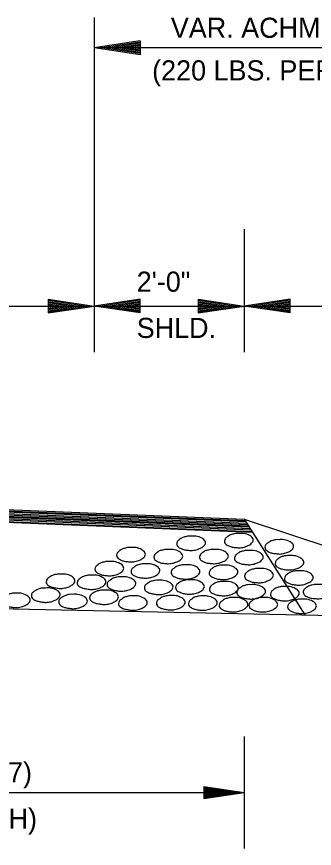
# Model space of a CAD drawing. Extents: x 1035 to 3550, y 35 to 1510.
# Drawn here: x 2489.7 to 2578.4, y 579 to 826.9 of the extents above; entities that cross this region are included whole.
import ezdxf

# ---------------------------------------------------------------- set-up
doc = ezdxf.new("R2010")
doc.units = 0
doc.layers.add('Default', color=7, linetype='Continuous')

msp = doc.modelspace()

# ---------------------------------------------------------------- linework, layer by layer
at = {"layer": 'Default'}
for p, q in [((2512.84, 826.63), (2512.84, 763.6)), ((2526.54, 819.67), (2512.84, 817.63)), ((2526.54, 819.34), (2515.11, 817.63)), ((2526.54, 818.99), (2517.48, 817.63)), ((2526.54, 818.66), (2519.76, 817.63)), ((2526.54, 818.27), (2522.08, 817.63)), ((2526.54, 819.67), (2526.54, 815.57)), ((2526.54, 815.57), (2512.84, 817.63)), ((2745.94, 817.63), (2512.84, 817.63)), ((2526.54, 815.92), (2515.11, 817.63)), ((2526.54, 816.26), (2517.48, 817.63)), ((2526.54, 816.62), (2519.76, 817.63)), ((2526.54, 816.95), (2522.08, 817.63)), ((2526.54, 817.96), (2524.35, 817.63)), ((2526.54, 817.3), (2524.35, 817.63)), ((2512.84, 763.6), (2512.84, 726.95)), ((2557.51, 763.6), (2557.51, 726.95)), ((2499.16, 742.69), (2512.84, 740.65)), ((2499.16, 742.69), (2499.16, 738.59)), ((2499.16, 742.36), (2510.55, 740.65)), ((2499.16, 742), (2508.21, 740.65)), ((2499.16, 741.67), (2505.94, 740.65)), ((2499.16, 741.3), (2503.58, 740.65)), ((2526.54, 742.69), (2512.84, 740.65)), ((2526.54, 742.36), (2515.12, 740.65)), ((2526.54, 742), (2517.47, 740.65)), ((2526.54, 741.67), (2519.76, 740.65)), ((2526.54, 741.3), (2522.07, 740.65)), ((2526.54, 738.59), (2526.54, 742.69)), ((2543.83, 742.69), (2557.51, 740.65)), ((2543.83, 742.69), (2543.83, 738.59)), ((2543.83, 742.36), (2555.22, 740.65)), ((2543.83, 742), (2552.88, 740.65)), ((2543.83, 741.67), (2550.61, 740.65)), ((2543.83, 741.3), (2548.25, 740.65)), ((2571.21, 742.69), (2557.51, 740.65)), ((2571.21, 742.36), (2559.79, 740.65)), ((2571.21, 742), (2562.14, 740.65)), ((2571.21, 741.67), (2564.43, 740.65)), ((2571.21, 741.3), (2566.74, 740.65)), ((2571.21, 738.59), (2571.21, 742.69)), ((2335.41, 740.65), (2512.84, 740.65)), ((2499.16, 740.97), (2501.31, 740.65)), ((2499.16, 738.59), (2512.84, 740.65)), ((2499.16, 739.96), (2503.58, 740.65)), ((2499.16, 739.27), (2508.21, 740.65)), ((2499.16, 738.93), (2510.55, 740.65)), ((2499.16, 739.63), (2505.94, 740.65)), ((2499.16, 740.32), (2501.31, 740.65)), ((2512.84, 740.65), (2557.51, 740.65)), ((2526.54, 738.59), (2512.84, 740.65)), ((2526.54, 738.93), (2515.12, 740.65)), ((2526.54, 739.27), (2517.47, 740.65)), ((2526.54, 739.63), (2519.76, 740.65)), ((2526.54, 739.96), (2522.07, 740.65)), ((2526.54, 740.97), (2524.34, 740.65)), ((2526.54, 740.32), (2524.34, 740.65)), ((2543.83, 740.97), (2545.98, 740.65)), ((2543.83, 738.59), (2557.51, 740.65)), ((2543.83, 739.96), (2548.25, 740.65)), ((2543.83, 739.27), (2552.88, 740.65)), ((2543.83, 738.93), (2555.22, 740.65)), ((2543.83, 739.63), (2550.61, 740.65)), ((2543.83, 740.32), (2545.98, 740.65)), ((2557.51, 740.65), (2647.44, 740.65)), ((2571.21, 738.59), (2557.51, 740.65)), ((2571.21, 738.93), (2559.79, 740.65)), ((2571.21, 739.27), (2562.14, 740.65)), ((2571.21, 739.63), (2564.43, 740.65)), ((2571.21, 739.96), (2566.74, 740.65)), ((2571.21, 740.97), (2569.01, 740.65)), ((2571.21, 740.32), (2569.01, 740.65)), ((2512.84, 733.81), (2512.84, 726.95)), ((2330.33, 686.31), (2557.51, 677.18)), ((2330.33, 685.87), (2557.79, 676.73)), ((2330.33, 685.54), (2557.97, 676.45)), ((2330.33, 685.12), (2558.27, 675.98)), ((2330.33, 684.7), (2558.52, 675.59)), ((2330.33, 684.34), (2558.81, 675.13)), ((2330.33, 683.96), (2559.01, 674.8)), ((2330.33, 683.58), (2559.3, 674.35)), ((2330.33, 683.16), (2559.55, 673.96)), ((2330.33, 682.79), (2559.84, 673.5)), ((2330.33, 682.46), (2560.01, 673.24)), ((2557.51, 677.18), (2575.62, 648.63)), ((2557.51, 677.18), (2755.04, 611.33)), ((2261.14, 654.92), (2647.44, 647.2)), ((2557.51, 612.37), (2557.51, 579.01)), ((2545.51, 597.49), (2557.51, 595.69)), ((2545.51, 597.49), (2545.51, 593.89)), ((2355.29, 595.69), (2557.51, 595.69)), ((2545.51, 597.19), (2555.51, 595.69)), ((2545.51, 596.88), (2553.44, 595.69)), ((2545.51, 596.58), (2551.44, 595.69)), ((2545.51, 596.27), (2549.41, 595.69)), ((2545.51, 595.97), (2547.41, 595.69)), ((2545.51, 593.89), (2557.51, 595.69)), ((2545.51, 595.1), (2549.41, 595.69)), ((2545.51, 594.5), (2553.44, 595.69)), ((2545.51, 594.19), (2555.51, 595.69)), ((2545.51, 594.8), (2551.44, 595.69)), ((2545.51, 595.41), (2547.41, 595.69))]:
    msp.add_line(p, q, dxfattribs=at)
for points in [[(2541.65, 672.07), (2543.13, 672.05), (2544.97, 671.43), (2545.86, 670.55), (2546.01, 670.04), (2545.51, 669.14), (2544.98, 668.7), (2544, 668.25), (2542.51, 667.86), (2541.76, 667.81), (2540.64, 667.89), (2539.42, 668.09), (2538.47, 668.48), (2537.57, 669.18), (2537.43, 669.79), (2537.71, 670.59), (2538.38, 671.16), (2539.03, 671.6), (2540.04, 671.89), (2540.65, 672.05), (2541.65, 672.07)], [(2555.88, 672.88), (2557.36, 672.86), (2559.2, 672.24), (2560.09, 671.36), (2560.24, 670.85), (2559.74, 669.95), (2559.21, 669.51), (2558.23, 669.06), (2556.74, 668.67), (2555.99, 668.62), (2554.87, 668.7), (2553.65, 668.9), (2552.7, 669.29), (2551.8, 669.99), (2551.66, 670.6), (2551.94, 671.4), (2552.61, 671.97), (2553.26, 672.41), (2554.27, 672.7), (2554.88, 672.86), (2555.88, 672.88)], [(2567.9, 671.02), (2569.43, 671.01), (2571.25, 670.37), (2572.14, 669.54), (2572.26, 669), (2571.8, 668.08), (2571.28, 667.69), (2570.28, 667.17), (2568.82, 666.83), (2568.06, 666.75), (2566.95, 666.86), (2565.69, 667.07), (2564.74, 667.44), (2563.86, 668.17), (2563.71, 668.75), (2563.97, 669.57), (2564.67, 670.1), (2565.31, 670.52), (2566.33, 670.87), (2566.96, 671.01), (2567.9, 671.02)], [(2523.75, 668.66), (2525.23, 668.64), (2527.07, 668.02), (2527.96, 667.14), (2528.11, 666.63), (2527.61, 665.73), (2527.08, 665.29), (2526.1, 664.84), (2524.61, 664.45), (2523.86, 664.4), (2522.74, 664.48), (2521.52, 664.68), (2520.57, 665.07), (2519.67, 665.77), (2519.53, 666.38), (2519.81, 667.18), (2520.48, 667.75), (2521.13, 668.19), (2522.14, 668.48), (2522.75, 668.64), (2523.75, 668.66)], [(2534.86, 668.12), (2536.34, 668.1), (2538.18, 667.48), (2539.07, 666.6), (2539.22, 666.09), (2538.72, 665.19), (2538.19, 664.75), (2537.21, 664.3), (2535.72, 663.91), (2534.97, 663.86), (2533.85, 663.94), (2532.63, 664.14), (2531.68, 664.53), (2530.78, 665.23), (2530.64, 665.84), (2530.92, 666.64), (2531.59, 667.21), (2532.24, 667.65), (2533.25, 667.94), (2533.86, 668.1), (2534.86, 668.12)], [(2548.45, 668.12), (2549.93, 668.1), (2551.77, 667.48), (2552.66, 666.6), (2552.81, 666.09), (2552.31, 665.19), (2551.78, 664.75), (2550.8, 664.3), (2549.31, 663.91), (2548.56, 663.86), (2547.44, 663.94), (2546.22, 664.14), (2545.27, 664.53), (2544.37, 665.23), (2544.23, 665.84), (2544.51, 666.64), (2545.18, 667.21), (2545.83, 667.65), (2546.84, 667.94), (2547.45, 668.1), (2548.45, 668.12)], [(2558.85, 667.82), (2560.33, 667.8), (2562.17, 667.18), (2563.06, 666.3), (2563.21, 665.79), (2562.71, 664.89), (2562.18, 664.45), (2561.2, 664), (2559.71, 663.61), (2558.96, 663.56), (2557.84, 663.64), (2556.62, 663.84), (2555.67, 664.23), (2554.77, 664.93), (2554.63, 665.54), (2554.91, 666.34), (2555.58, 666.91), (2556.23, 667.35), (2557.24, 667.64), (2557.85, 667.8), (2558.85, 667.82)], [(2517.27, 664.5), (2518.8, 664.49), (2520.62, 663.85), (2521.51, 663.02), (2521.63, 662.48), (2521.17, 661.56), (2520.65, 661.17), (2519.65, 660.65), (2518.19, 660.31), (2517.43, 660.23), (2516.32, 660.34), (2515.06, 660.55), (2514.11, 660.92), (2513.23, 661.65), (2513.08, 662.23), (2513.34, 663.05), (2514.04, 663.58), (2514.68, 664), (2515.7, 664.35), (2516.33, 664.49), (2517.27, 664.5)], [(2570.94, 666.26), (2572.45, 666.24), (2574.26, 665.62), (2575.16, 664.75), (2575.32, 664.25), (2574.84, 663.31), (2574.31, 662.89), (2573.32, 662.44), (2571.84, 662.05), (2571.08, 661.99), (2569.96, 662.07), (2568.73, 662.29), (2567.78, 662.67), (2566.9, 663.38), (2566.75, 663.98), (2567.01, 664.78), (2567.7, 665.36), (2568.34, 665.79), (2569.37, 666.1), (2569.99, 666.24), (2570.94, 666.26)], [(2528.03, 663.8), (2529.56, 663.79), (2531.38, 663.15), (2532.27, 662.32), (2532.39, 661.78), (2531.93, 660.86), (2531.41, 660.47), (2530.41, 659.95), (2528.95, 659.61), (2528.19, 659.53), (2527.08, 659.64), (2525.82, 659.85), (2524.87, 660.22), (2523.99, 660.95), (2523.84, 661.53), (2524.1, 662.35), (2524.8, 662.88), (2525.44, 663.3), (2526.46, 663.65), (2527.09, 663.79), (2528.03, 663.8)], [(2539.95, 663.53), (2541.49, 663.49), (2543.32, 662.88), (2544.21, 662.01), (2544.31, 661.51), (2543.85, 660.56), (2543.33, 660.15), (2542.35, 659.67), (2540.87, 659.31), (2540.11, 659.25), (2539, 659.34), (2537.78, 659.56), (2536.82, 659.93), (2535.93, 660.64), (2535.77, 661.24), (2536.04, 662.07), (2536.73, 662.6), (2537.38, 663.04), (2538.38, 663.36), (2539.02, 663.49), (2539.95, 663.53)], [(2551.27, 663.41), (2552.78, 663.39), (2554.6, 662.75), (2555.52, 661.9), (2555.66, 661.4), (2555.16, 660.46), (2554.63, 660.04), (2553.67, 659.56), (2552.16, 659.19), (2551.42, 659.14), (2550.29, 659.22), (2549.07, 659.43), (2548.12, 659.82), (2547.23, 660.53), (2547.09, 661.15), (2547.36, 661.93), (2548.04, 662.49), (2548.7, 662.93), (2549.68, 663.25), (2550.3, 663.39), (2551.27, 663.41)], [(2561.87, 662.45), (2563.35, 662.43), (2565.19, 661.81), (2566.08, 660.93), (2566.23, 660.42), (2565.73, 659.52), (2565.2, 659.08), (2564.22, 658.63), (2562.73, 658.24), (2561.98, 658.19), (2560.86, 658.27), (2559.64, 658.47), (2558.69, 658.86), (2557.79, 659.56), (2557.65, 660.17), (2557.93, 660.97), (2558.6, 661.54), (2559.25, 661.98), (2560.26, 662.27), (2560.87, 662.43), (2561.87, 662.45)], [(2502.73, 660.75), (2504.26, 660.74), (2506.08, 660.1), (2506.97, 659.27), (2507.09, 658.73), (2506.63, 657.81), (2506.11, 657.42), (2505.11, 656.9), (2503.65, 656.56), (2502.89, 656.48), (2501.78, 656.59), (2500.52, 656.8), (2499.57, 657.17), (2498.69, 657.9), (2498.54, 658.48), (2498.8, 659.3), (2499.5, 659.83), (2500.14, 660.25), (2501.16, 660.6), (2501.79, 660.74), (2502.73, 660.75)], [(2511.96, 660.44), (2513.49, 660.43), (2515.31, 659.79), (2516.2, 658.96), (2516.32, 658.42), (2515.86, 657.5), (2515.34, 657.11), (2514.34, 656.59), (2512.88, 656.25), (2512.12, 656.17), (2511.01, 656.28), (2509.75, 656.49), (2508.8, 656.86), (2507.92, 657.59), (2507.77, 658.17), (2508.03, 658.99), (2508.73, 659.52), (2509.37, 659.94), (2510.39, 660.29), (2511.02, 660.43), (2511.96, 660.44)], [(2520.88, 659.92), (2522.41, 659.91), (2524.23, 659.27), (2525.12, 658.44), (2525.24, 657.9), (2524.78, 656.98), (2524.26, 656.59), (2523.26, 656.07), (2521.8, 655.73), (2521.04, 655.65), (2519.93, 655.76), (2518.67, 655.97), (2517.72, 656.34), (2516.84, 657.07), (2516.69, 657.65), (2516.95, 658.47), (2517.65, 659), (2518.29, 659.42), (2519.31, 659.77), (2519.94, 659.91), (2520.88, 659.92)], [(2573.74, 661.71), (2575.22, 661.69), (2577.06, 661.1), (2577.93, 660.23), (2578.09, 659.73), (2577.62, 658.78), (2577.08, 658.38), (2576.09, 657.91), (2574.63, 657.53), (2573.85, 657.47), (2572.74, 657.55), (2571.51, 657.75), (2570.56, 658.16), (2569.66, 658.87), (2569.53, 659.44), (2569.8, 660.26), (2570.48, 660.81), (2571.11, 661.24), (2572.14, 661.59), (2572.76, 661.69), (2573.74, 661.71)], [(2531.98, 658.93), (2533.52, 658.88), (2535.34, 658.27), (2536.23, 657.4), (2536.34, 656.9), (2535.87, 655.95), (2535.36, 655.55), (2534.38, 655.06), (2532.9, 654.71), (2532.13, 654.64), (2531.03, 654.74), (2529.81, 654.96), (2528.84, 655.33), (2527.96, 656.03), (2527.8, 656.64), (2528.07, 657.46), (2528.75, 657.99), (2529.41, 658.43), (2530.4, 658.76), (2531.04, 658.88), (2531.98, 658.93)], [(2541.26, 659.05), (2542.78, 659.04), (2544.6, 658.4), (2545.52, 657.54), (2545.66, 657.04), (2545.16, 656.11), (2544.63, 655.69), (2543.66, 655.2), (2542.15, 654.83), (2541.42, 654.78), (2540.28, 654.86), (2539.07, 655.08), (2538.12, 655.47), (2537.23, 656.17), (2537.09, 656.79), (2537.35, 657.57), (2538.04, 658.13), (2538.69, 658.57), (2539.67, 658.9), (2540.3, 659.04), (2541.26, 659.05)], [(2551.36, 658.57), (2552.87, 658.55), (2554.7, 657.92), (2555.62, 657.06), (2555.76, 656.56), (2555.26, 655.63), (2554.73, 655.2), (2553.76, 654.72), (2552.25, 654.35), (2551.52, 654.3), (2550.38, 654.38), (2549.17, 654.6), (2548.21, 654.99), (2547.33, 655.69), (2547.19, 656.31), (2547.45, 657.09), (2548.14, 657.65), (2548.79, 658.09), (2549.77, 658.41), (2550.4, 658.55), (2551.36, 658.57)], [(2559.53, 657.6), (2561.04, 657.59), (2562.86, 656.95), (2563.78, 656.09), (2563.92, 655.59), (2563.42, 654.66), (2562.89, 654.24), (2561.93, 653.76), (2560.42, 653.38), (2559.68, 653.33), (2558.55, 653.41), (2557.33, 653.63), (2556.38, 654.02), (2555.49, 654.72), (2555.35, 655.34), (2555.62, 656.12), (2556.3, 656.68), (2556.96, 657.12), (2557.94, 657.45), (2558.56, 657.59), (2559.53, 657.6)], [(2569.53, 657.06), (2571.04, 657.04), (2572.86, 656.4), (2573.78, 655.55), (2573.92, 655.05), (2573.42, 654.11), (2572.89, 653.69), (2571.93, 653.21), (2570.42, 652.83), (2569.68, 652.79), (2568.55, 652.87), (2567.33, 653.08), (2566.38, 653.47), (2565.49, 654.18), (2565.35, 654.8), (2565.62, 655.58), (2566.3, 656.14), (2566.96, 656.57), (2567.94, 656.9), (2568.56, 657.04), (2569.53, 657.06)], [(2579.33, 657.67), (2580.81, 657.66), (2582.65, 657.03), (2583.52, 656.16), (2583.68, 655.66), (2583.21, 654.73), (2582.67, 654.32), (2581.68, 653.84), (2580.22, 653.46), (2579.44, 653.42), (2578.35, 653.48), (2577.1, 653.68), (2576.15, 654.09), (2575.26, 654.79), (2575.12, 655.38), (2575.4, 656.21), (2576.09, 656.77), (2576.7, 657.2), (2577.73, 657.5), (2578.37, 657.66), (2579.33, 657.67)], [(2489.42, 655.04), (2490.95, 655.03), (2492.77, 654.39), (2493.66, 653.56), (2493.78, 653.02), (2493.32, 652.1), (2492.8, 651.71), (2491.8, 651.19), (2490.34, 650.85), (2489.58, 650.77), (2488.47, 650.88), (2487.21, 651.09), (2486.26, 651.46), (2485.38, 652.19), (2485.23, 652.77), (2485.49, 653.59), (2486.19, 654.12), (2486.83, 654.54), (2487.85, 654.89), (2488.48, 655.03), (2489.42, 655.04)], [(2498.33, 656.6), (2499.86, 656.59), (2501.68, 655.95), (2502.57, 655.12), (2502.69, 654.58), (2502.23, 653.66), (2501.71, 653.27), (2500.71, 652.75), (2499.25, 652.41), (2498.49, 652.33), (2497.38, 652.44), (2496.12, 652.65), (2495.17, 653.02), (2494.29, 653.75), (2494.14, 654.33), (2494.4, 655.15), (2495.1, 655.68), (2495.74, 656.1), (2496.76, 656.45), (2497.39, 656.59), (2498.33, 656.6)], [(2506.46, 654.72), (2507.99, 654.71), (2509.81, 654.07), (2510.7, 653.24), (2510.82, 652.7), (2510.36, 651.78), (2509.84, 651.39), (2508.84, 650.87), (2507.38, 650.53), (2506.62, 650.45), (2505.51, 650.56), (2504.25, 650.77), (2503.3, 651.14), (2502.42, 651.87), (2502.27, 652.45), (2502.53, 653.27), (2503.23, 653.8), (2503.87, 654.22), (2504.89, 654.57), (2505.52, 654.71), (2506.46, 654.72)], [(2515.68, 655.97), (2517.21, 655.96), (2519.03, 655.32), (2519.92, 654.49), (2520.04, 653.95), (2519.58, 653.03), (2519.06, 652.64), (2518.06, 652.12), (2516.6, 651.78), (2515.84, 651.7), (2514.73, 651.81), (2513.47, 652.02), (2512.52, 652.39), (2511.64, 653.12), (2511.49, 653.7), (2511.75, 654.52), (2512.45, 655.05), (2513.09, 655.47), (2514.11, 655.82), (2514.74, 655.96), (2515.68, 655.97)], [(2524.27, 654.25), (2525.8, 654.24), (2527.62, 653.6), (2528.51, 652.77), (2528.63, 652.23), (2528.17, 651.31), (2527.65, 650.92), (2526.65, 650.4), (2525.19, 650.06), (2524.43, 649.98), (2523.32, 650.09), (2522.06, 650.3), (2521.11, 650.67), (2520.23, 651.4), (2520.08, 651.98), (2520.34, 652.8), (2521.04, 653.33), (2521.68, 653.75), (2522.7, 654.1), (2523.33, 654.24), (2524.27, 654.25)], [(2535.58, 654.36), (2537.12, 654.32), (2538.94, 653.71), (2539.83, 652.84), (2539.94, 652.34), (2539.47, 651.39), (2538.96, 650.98), (2537.98, 650.5), (2536.5, 650.14), (2535.73, 650.08), (2534.63, 650.17), (2533.41, 650.39), (2532.44, 650.76), (2531.56, 651.46), (2531.4, 652.07), (2531.67, 652.9), (2532.35, 653.43), (2533.01, 653.86), (2534, 654.19), (2534.64, 654.32), (2535.58, 654.36)], [(2545.11, 654.24), (2546.63, 654.22), (2548.45, 653.58), (2549.37, 652.73), (2549.51, 652.23), (2549.01, 651.29), (2548.48, 650.87), (2547.51, 650.39), (2546, 650.02), (2545.27, 649.97), (2544.13, 650.05), (2542.92, 650.26), (2541.97, 650.65), (2541.08, 651.36), (2540.94, 651.98), (2541.2, 652.76), (2541.89, 653.32), (2542.54, 653.76), (2543.52, 654.08), (2544.15, 654.22), (2545.11, 654.24)], [(2554.25, 653.76), (2555.76, 653.74), (2557.58, 653.1), (2558.5, 652.24), (2558.64, 651.74), (2558.14, 650.81), (2557.61, 650.39), (2556.64, 649.91), (2555.13, 649.53), (2554.4, 649.49), (2553.26, 649.56), (2552.05, 649.78), (2551.1, 650.17), (2550.21, 650.87), (2550.07, 651.5), (2550.33, 652.27), (2551.02, 652.84), (2551.67, 653.27), (2552.66, 653.6), (2553.28, 653.74), (2554.25, 653.76)], [(2563.13, 653.76), (2564.64, 653.74), (2566.46, 653.1), (2567.38, 652.24), (2567.52, 651.74), (2567.02, 650.81), (2566.49, 650.39), (2565.53, 649.91), (2564.02, 649.53), (2563.28, 649.49), (2562.15, 649.56), (2560.93, 649.78), (2559.98, 650.17), (2559.09, 650.87), (2558.95, 651.5), (2559.22, 652.27), (2559.9, 652.84), (2560.56, 653.27), (2561.54, 653.6), (2562.16, 653.74), (2563.13, 653.76)], [(2574.66, 653.27), (2576.17, 653.26), (2577.99, 652.62), (2578.91, 651.76), (2579.05, 651.26), (2578.55, 650.33), (2578.02, 649.91), (2577.06, 649.42), (2575.55, 649.05), (2574.81, 649), (2573.68, 649.08), (2572.46, 649.3), (2571.51, 649.69), (2570.62, 650.39), (2570.48, 651.01), (2570.75, 651.79), (2571.43, 652.35), (2572.09, 652.79), (2573.07, 653.12), (2573.69, 653.26), (2574.66, 653.27)]]:
    msp.add_spline(points, degree=3, dxfattribs=at)

# ---------------------------------------------------------------- texts
for s, p in [('VAR. ACHM SURFACE COURSE (1/2")', (2535.68, 820.6)), ('(220 LBS. PER SQ. YD.) & TACK COAT', (2530.11, 807.9)), ('2\'-0"', (2525.51, 744.93)), ('SHLD.', (2525.51, 731.14)), ('BASE COURSE (CLASS 7)', (2395.78, 598.67)), ('(10" COMPACTED DEPTH)', (2395.78, 584.88))]:
    msp.add_text(s, height=6, dxfattribs=at).set_placement(p)

doc.saveas('drawing.dxf')
